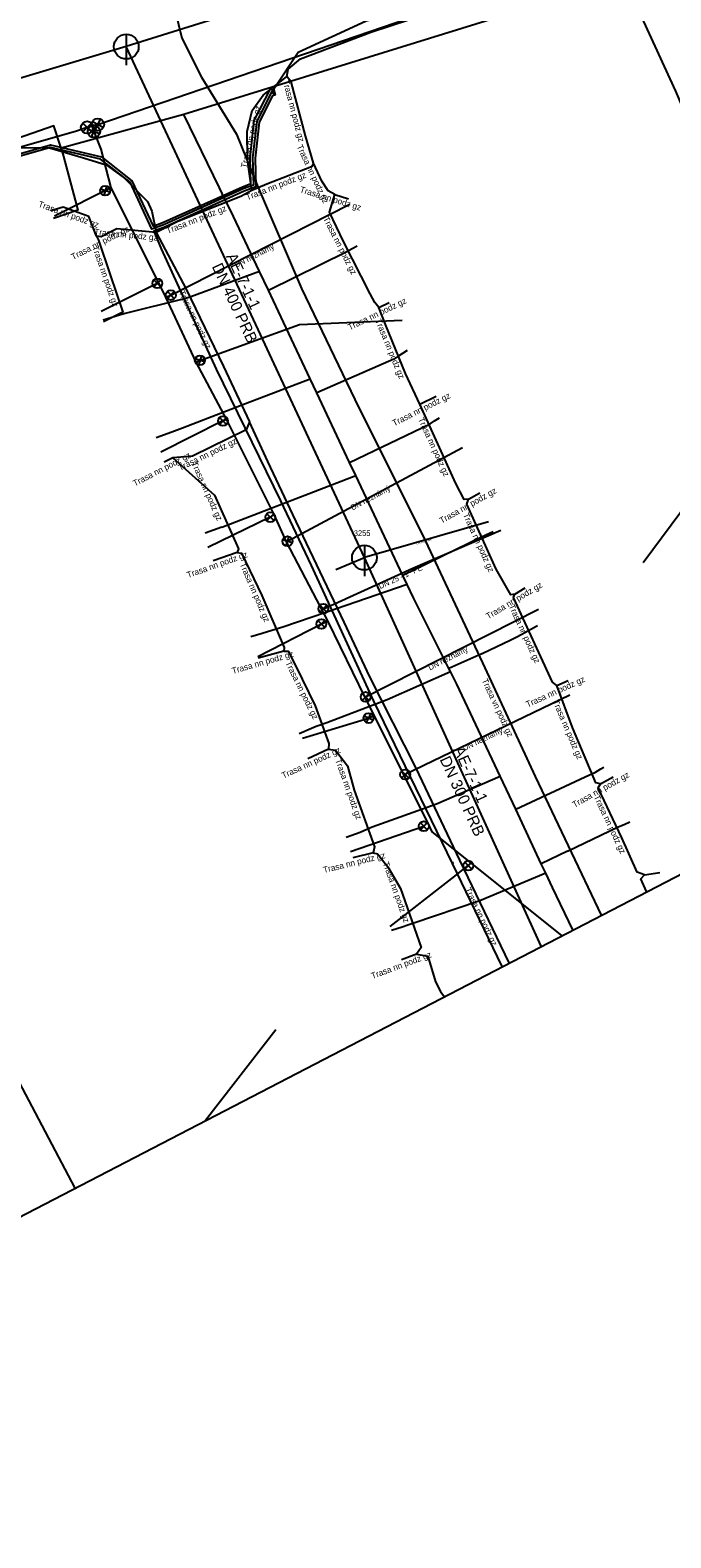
# Model space of a CAD drawing. Extents: x -493753 to -49291, y -1127285 to -112662.
# Drawn here: x -493223.7 to -493171.7, y -1127147 to -1127024.8 of the extents above; entities that cross this region are included whole.
import ezdxf

# ---------------------------------------------------------------- set-up
doc = ezdxf.new("R2010")
doc.units = 0
for name, color, linetype in [('Vrstva 1', 7, 'Continuous'), ('Vrstva 14', 7, 'Continuous'), ('Vrstva 15', 7, 'Continuous'), ('Vrstva 17', 7, 'Continuous'), ('Vrstva 19', 7, 'Continuous'), ('Vrstva 20', 7, 'Continuous'), ('Vrstva 22', 7, 'Continuous'), ('Vrstva 24', 7, 'Continuous'), ('Vrstva 25', 7, 'Continuous'), ('Vrstva 26', 7, 'Continuous'), ('Vrstva 39', 7, 'Continuous'), ('Vrstva 5', 7, 'Continuous'), ('Vrstva 6', 7, 'Continuous'), ('Vrstva 9', 7, 'Continuous')]:
    doc.layers.add(name, color=color, linetype=linetype)

# ---------------------------------------------------------------- blocks, each defined once
blk = doc.blocks.new('_UZAVE')
at = {"layer": 'Vrstva 1'}
for p, q in [((-0.035, -0.035), (0.035, 0.035)), ((0.035, -0.035), (-0.035, 0.035))]:
    blk.add_line(p, q, dxfattribs=at)
for radius in [0.05, 0.0025]:
    blk.add_circle((0, 0), radius, dxfattribs=at)
blk = doc.blocks.new('_UZAV0')
at = {"layer": 'Vrstva 1'}
for p, q in [((-0.035, -0.035), (0.035, 0.035)), ((0.035, -0.035), (-0.035, 0.035))]:
    blk.add_line(p, q, dxfattribs=at)
for radius in [0.05, 0.0025]:
    blk.add_circle((0, 0), radius, dxfattribs=at)
blk = doc.blocks.new('_SACH0')
at = {"layer": 'Vrstva 1'}
blk.add_line((0, 0.05), (0, -0.075), dxfattribs=at)
blk.add_circle((0, 0), 0.05, dxfattribs=at)

msp = doc.modelspace()

# ---------------------------------------------------------------- linework, layer by layer
at = {"layer": 'Vrstva 1'}
for p, q in [((-493204.35, -1127045.83), (-493197.99, -1127042.7)), ((-493194.18, -1127051.44), (-493200.42, -1127054.15)), ((-493197.76, -1127059.8), (-493191.23, -1127056.67)), ((-493208.11, -1127065.04), (-493197.25, -1127060.86)), ((-493208.11, -1127065.04), (-493209.47, -1127065.53)), ((-493187.07, -1127065.86), (-493193.43, -1127068.97)), ((-493184.28, -1127087.92), (-493178.65, -1127085.3)), ((-493180.09, -1127091.32), (-493182.21, -1127092.33))]:
    msp.add_line(p, q, dxfattribs=at)
for points in [[(-493753.13, -1126773.63), (-493540.88, -1127284.87), (-492737.61, -1126868.64), (-492950.39, -1126535.73)], [(-493131.42, -1127030.32), (-493131.54, -1127030.08), (-493135.12, -1127022.73), (-493135.45, -1127022.1), (-493138.54, -1127016.22), (-493141.06, -1127011.41), (-493141.75, -1127010.11), (-493148.64, -1127012.24), (-493150.28, -1127012.75), (-493211.21, -1127031.6)], [(-493211.21, -1127031.6), (-493221.15, -1127034.33), (-493221.76, -1127032.53), (-493224.08, -1127033.32), (-493235.06, -1127037.06), (-493243.7, -1127040), (-493243.18, -1127041.53), (-493248.45, -1127043.29), (-493250.96, -1127044.13), (-493295.19, -1127058.95), (-493308.31, -1127063.27)], [(-493179.64, -1127097.68), (-493181.3, -1127094.25), (-493181.85, -1127093.09), (-493182.21, -1127092.33), (-493184.28, -1127087.92), (-493185.55, -1127085.23), (-493189.06, -1127077.78), (-493189.57, -1127076.76), (-493189.7, -1127076.5), (-493192.58, -1127070.78), (-493193.08, -1127069.71), (-493193.43, -1127068.97), (-493197.25, -1127060.86), (-493197.76, -1127059.8), (-493200.42, -1127054.15), (-493200.95, -1127053.02), (-493203.12, -1127048.42), (-493204.35, -1127045.83), (-493205.07, -1127044.33), (-493207.43, -1127039.35), (-493207.87, -1127038.45), (-493208.31, -1127037.55), (-493211.21, -1127031.6)], [(-493221.15, -1127034.33), (-493220.97, -1127035.01), (-493219.8, -1127039.36), (-493221.78, -1127040.04)], [(-493197.99, -1127042.7), (-493197.56, -1127042.47), (-493197.14, -1127042.24)], [(-493205.07, -1127044.33), (-493210.63, -1127046.37), (-493211.24, -1127046.56), (-493211.3, -1127046.58), (-493215.97, -1127047.73)], [(-493215.97, -1127047.73), (-493216.43, -1127047.87), (-493217.76, -1127048.26)], [(-493193.08, -1127050.72), (-493193.86, -1127051.22), (-493194.18, -1127051.44)], [(-493211.75, -1127057.16), (-493211.32, -1127057), (-493206.19, -1127055.03), (-493200.95, -1127053.02)], [(-493191.23, -1127056.67), (-493190.87, -1127056.44), (-493190.48, -1127056.18)], [(-493213.46, -1127057.79), (-493212.17, -1127057.32), (-493211.75, -1127057.16)], [(-493186.11, -1127065.42), (-493186.7, -1127065.69), (-493186.76, -1127065.72), (-493187.07, -1127065.86)], [(-493193.08, -1127069.71), (-493199.69, -1127071.96), (-493203.17, -1127073.16), (-493204.43, -1127073.54)], [(-493204.43, -1127073.54), (-493204.86, -1127073.67), (-493205.76, -1127073.95)], [(-493182.51, -1127073.06), (-493183.8, -1127073.76), (-493184.24, -1127074)], [(-493184.24, -1127074), (-493184.69, -1127074.21), (-493187.01, -1127075.31), (-493187.03, -1127075.31), (-493189.7, -1127076.5)], [(-493200.46, -1127081.17), (-493199.6, -1127080.88), (-493194.7, -1127079.03), (-493189.57, -1127076.76)], [(-493201.86, -1127081.77), (-493200.86, -1127081.34), (-493200.46, -1127081.17)], [(-493178.65, -1127085.3), (-493177.82, -1127084.92), (-493177.38, -1127084.64), (-493177.14, -1127084.49)], [(-493196.6, -1127089.65), (-493195.94, -1127089.35), (-493190.7, -1127087.47), (-493185.55, -1127085.23)], [(-493180.09, -1127091.32), (-493175.98, -1127089.35), (-493175.48, -1127089.14), (-493175.03, -1127088.94)], [(-493198.04, -1127090.19), (-493196.89, -1127089.76), (-493196.6, -1127089.65)], [(-493181.85, -1127093.09), (-493187.2, -1127095.33), (-493192.62, -1127097.17), (-493193.04, -1127097.32)], [(-493193.04, -1127097.32), (-493193.5, -1127097.46), (-493194.35, -1127097.74)]]:
    msp.add_lwpolyline(points, dxfattribs=at)
at = {"layer": 'Vrstva 14'}
for points in [[(-493161.26, -1127050.88), (-493173.95, -1127067.95)], [(-493238.01, -1127084.61), (-493220.05, -1127118.62)], [(-493209.44, -1127113.12), (-493203.73, -1127105.78)]]:
    msp.add_lwpolyline(points, dxfattribs=at)
at = {"layer": 'Vrstva 15'}
for p, q in [((-493183.43, -1127015.92), (-493215.87, -1127026.1)), ((-493215.87, -1127026.1), (-493243.41, -1127034.33)), ((-493196.56, -1127067.52), (-493215.87, -1127026.1)), ((-493186.5, -1127064.61), (-493196.56, -1127067.52)), ((-493198.87, -1127068.47), (-493196.56, -1127067.52)), ((-493182.21, -1127099.01), (-493196.56, -1127067.52))]:
    msp.add_line(p, q, dxfattribs=at)
at = {"layer": 'Vrstva 20'}
for p, q in [((-493218.18, -1127032.42), (-493144.22, -1127007.09)), ((-493218.66, -1127032.52), (-493219.05, -1127032.65)), ((-493218.66, -1127032.52), (-493218.18, -1127032.42)), ((-493218.66, -1127032.52), (-493218.5, -1127032.97)), ((-493217.14, -1127037.55), (-493221.7, -1127039.84)), ((-493201.81, -1127048.63), (-493193.49, -1127048.27)), ((-493194.46, -1127097.43), (-493189.46, -1127093.52))]:
    msp.add_line(p, q, dxfattribs=at)
for points in [[(-493219.05, -1127032.65), (-493219.91, -1127032.94), (-493249.48, -1127041.42), (-493252.24, -1127042.48), (-493297.85, -1127056.18)], [(-493218.5, -1127032.97), (-493217.94, -1127034.41), (-493217.14, -1127037.55), (-493213.27, -1127045.25), (-493212.7, -1127046.4), (-493210.24, -1127051.68), (-493207.75, -1127056.34), (-493203.9, -1127064.03), (-493202.9, -1127066.25), (-493199.52, -1127072.69), (-493196.53, -1127078.85), (-493193.45, -1127085), (-493191.29, -1127089.33)], [(-493212.7, -1127046.4), (-493212.26, -1127046.24), (-493197.73, -1127038.88)], [(-493213.27, -1127045.25), (-493213.36, -1127045.29), (-493217.91, -1127047.58)], [(-493210.24, -1127051.68), (-493209.9, -1127051.53), (-493201.81, -1127048.63)], [(-493207.75, -1127056.34), (-493208.03, -1127056.44), (-493213.06, -1127058.98)], [(-493202.9, -1127066.25), (-493202.8, -1127066.19), (-493188.61, -1127058.6)], [(-493203.9, -1127064.03), (-493204.19, -1127064.24), (-493209.26, -1127066.69)], [(-493199.99, -1127071.76), (-493199.89, -1127071.66), (-493192.64, -1127068.38), (-493185.48, -1127065.29)], [(-493196.53, -1127078.85), (-493196.46, -1127078.81), (-493182.44, -1127071.69)], [(-493199.52, -1127072.69), (-493200.05, -1127072.9), (-493205.21, -1127075.57)], [(-493179.9, -1127078.67), (-493193.25, -1127085.1), (-493193.36, -1127085.17)], [(-493201.57, -1127082.15), (-493196.22, -1127080.53), (-493195.79, -1127080.32)], [(-493197.68, -1127091.34), (-493191.74, -1127089.29), (-493191.47, -1127088.98)], [(-493191.29, -1127089.33), (-493191.08, -1127089.75), (-493180.56, -1127098.16)], [(-493189.46, -1127093.52), (-493188.13, -1127092.48), (-493187.88, -1127092.19)]]:
    msp.add_lwpolyline(points, dxfattribs=at)
at = {"layer": 'Vrstva 25'}
for points in [[(-493203.78, -1127030.01), (-493203.91, -1127029.51), (-493201.93, -1127026.54), (-493196.42, -1127024.02), (-493192.45, -1127022.88), (-493192.52, -1127022.41), (-493192.27, -1127022.81), (-493171.2, -1127015.41), (-493171.17, -1127015.14), (-493171, -1127015.35), (-493150.3, -1127008.23), (-493147.93, -1127007.71), (-493147.3, -1127007.81), (-493147.29, -1127008.43), (-493147.1, -1127007.84), (-493145.51, -1127008.07), (-493142.62, -1127008.33), (-493140.69, -1127009.48), (-493138.74, -1127011.55), (-493132.11, -1127025.55), (-493132.31, -1127026.61)], [(-493260.22, -1127046.57), (-493260.09, -1127046.32), (-493254.57, -1127044.51), (-493239.33, -1127039.5), (-493225.18, -1127034.99), (-493225.11, -1127034.65), (-493224.84, -1127034.88), (-493222.03, -1127034.07), (-493217.89, -1127035.04), (-493215.41, -1127036.97), (-493213.7, -1127040.65), (-493212.86, -1127040.33), (-493206.46, -1127037.45), (-493205.76, -1127037.19), (-493205.83, -1127035.11), (-493205.49, -1127032.1), (-493204.16, -1127029.47), (-493203.78, -1127030.01)], [(-493203.78, -1127030.01), (-493204.09, -1127029.77), (-493205.29, -1127032.16), (-493205.63, -1127035.12), (-493205.56, -1127037.33), (-493206.38, -1127037.63), (-493212.78, -1127040.51), (-493213.8, -1127040.9), (-493215.57, -1127037.09), (-493217.97, -1127035.22), (-493222.03, -1127034.27), (-493224.95, -1127035.12), (-493239.27, -1127039.69)], [(-493203.78, -1127030.01), (-493204.02, -1127030.08), (-493205.1, -1127032.22), (-493205.43, -1127035.13), (-493205.36, -1127037.47), (-493206.31, -1127037.82), (-493212.7, -1127040.7), (-493213.63, -1127041.05), (-493213.04, -1127042.48), (-493208.58, -1127052.24), (-493203.36, -1127062.91), (-493200.89, -1127068.16), (-493195.82, -1127079.16), (-493189.43, -1127092.31), (-493185.4, -1127100.67)]]:
    msp.add_lwpolyline(points, dxfattribs=at)
at = {"layer": 'Vrstva 26'}
msp.add_line((-493189.31, -1127092.25), (-493189.33, -1127092.26), dxfattribs=at)
at = {"layer": 'Vrstva 39'}
msp.add_lwpolyline([(-493235.73, -1127025.17), (-493229.59, -1127023.36), (-493217.62, -1127019.87), (-493209.8, -1127017.48), (-493201.12, -1127014.06), (-493191.79, -1127010.53), (-493180.27, -1127008.11), (-493179.99, -1127008.93), (-493179.17, -1127010.93), (-493177.18, -1127016.55), (-493176.51, -1127018.4), (-493171.32, -1127029.71), (-493169.32, -1127034.4), (-493165.23, -1127043.1), (-493161.92, -1127050.08), (-493161.26, -1127050.88)], dxfattribs=at)
at = {"layer": 'Vrstva 5'}
for points in [[(-493202.84, -1127028.53), (-493202.74, -1127027.92), (-493201.75, -1127027.08), (-493196.03, -1127024.93), (-493188.11, -1127022.31), (-493177.11, -1127018.57), (-493168.04, -1127015.49), (-493159.49, -1127012.5), (-493152.14, -1127010.18), (-493147.23, -1127009.45), (-493145.09, -1127010.9)], [(-493205.68, -1127037.75), (-493206.04, -1127035.24), (-493206.07, -1127032.97), (-493205.67, -1127031.27), (-493204.77, -1127030.02), (-493203.15, -1127028.75), (-493202.84, -1127028.53)], [(-493200.7, -1127035.55), (-493201.35, -1127033.32), (-493202.5, -1127028.95), (-493202.84, -1127028.53)], [(-493294.6, -1127062.55), (-493296.76, -1127061.82), (-493296.08, -1127060.54), (-493294.79, -1127058.92), (-493292.58, -1127057.01), (-493290.97, -1127055.75), (-493287.24, -1127054.18), (-493281.83, -1127052.27), (-493275.52, -1127050.32), (-493268.05, -1127048.08), (-493261.13, -1127045.75), (-493255.54, -1127044), (-493242.37, -1127040.1), (-493234.97, -1127037.22), (-493227.14, -1127034.67), (-493224.59, -1127034.28), (-493222.11, -1127034.31), (-493219.35, -1127035.1), (-493217.51, -1127035.69), (-493216.02, -1127036.75), (-493214.15, -1127038.64), (-493213.79, -1127039.43), (-493213.44, -1127041.17)], [(-493200.7, -1127035.55), (-493200.86, -1127035.85), (-493204.47, -1127037.26), (-493205.68, -1127037.75)], [(-493198.96, -1127038.09), (-493199.51, -1127037.8), (-493200.02, -1127037.01), (-493200.7, -1127035.55)], [(-493205.68, -1127037.75), (-493206.58, -1127038.25), (-493211.7, -1127040.27), (-493213.44, -1127041.17)], [(-493195.38, -1127047.25), (-493195.71, -1127046.85), (-493196.1, -1127046.13), (-493198.26, -1127041.89), (-493199.38, -1127039.52), (-493198.96, -1127038.09)], [(-493198.96, -1127038.09), (-493197.84, -1127038.44)], [(-493218.28, -1127041.45), (-493218.92, -1127039.86), (-493220.99, -1127039.11), (-493221.99, -1127039.41)], [(-493216.65, -1127040.87), (-493217.92, -1127041.51), (-493218.28, -1127041.45)], [(-493218.28, -1127041.45), (-493218.12, -1127041.78), (-493217.18, -1127044.59), (-493216.14, -1127047.61), (-493217.71, -1127048.4)], [(-493213.44, -1127041.17), (-493216.65, -1127040.87)], [(-493213.44, -1127041.17), (-493211.02, -1127045.77), (-493208, -1127052.03), (-493205.89, -1127056.52)], [(-493195.38, -1127047.25), (-493194.54, -1127046.84)], [(-493192.05, -1127055.08), (-493193.22, -1127052.59), (-493194.85, -1127048.63), (-493195.38, -1127047.25)], [(-493192.05, -1127055.08), (-493190.75, -1127054.43)], [(-493188.11, -1127062.79), (-493188.47, -1127062.81), (-493189.13, -1127061.51), (-493192.05, -1127055.08)], [(-493205.89, -1127056.52), (-493206.15, -1127057.17), (-493210.51, -1127059.29), (-493212.11, -1127059.43)], [(-493184.83, -1127100.37), (-493188.82, -1127092.05), (-493192.35, -1127084.58), (-493196.11, -1127077.17), (-493198.19, -1127072.75), (-493202.36, -1127064.03), (-493204.38, -1127059.72), (-493205.89, -1127056.52)], [(-493212.11, -1127059.43), (-493212.79, -1127059.79)], [(-493212.11, -1127059.43), (-493208.72, -1127062.46), (-493206.77, -1127066.8), (-493206.88, -1127067.09)], [(-493188.11, -1127062.79), (-493187.19, -1127062.27)], [(-493184.35, -1127070.47), (-493184.69, -1127070.53), (-493185.87, -1127068.45), (-493188.25, -1127063.19), (-493188.11, -1127062.79)], [(-493206.88, -1127067.09), (-493208.83, -1127067.78)], [(-493206.88, -1127067.09), (-493206.54, -1127067.15), (-493204.89, -1127070.58), (-493203.07, -1127074.81), (-493203.1, -1127075.1)], [(-493184.35, -1127070.47), (-493183.51, -1127069.97)], [(-493180.95, -1127077.89), (-493181.3, -1127077.62), (-493184.47, -1127070.75), (-493184.35, -1127070.47)], [(-493203.1, -1127075.1), (-493205.17, -1127075.68)], [(-493203.1, -1127075.1), (-493202.73, -1127075.11), (-493202.13, -1127076.32), (-493200.55, -1127079.53), (-493199.45, -1127082.59), (-493199.47, -1127083.05)], [(-493180.95, -1127077.89), (-493180.02, -1127077.47)], [(-493177.4, -1127085.86), (-493177.78, -1127085.76), (-493179.69, -1127081.29), (-493180.95, -1127077.89)], [(-493199.47, -1127083.05), (-493201.14, -1127083.82)], [(-493199.47, -1127083.05), (-493198.9, -1127083.13), (-493197.94, -1127084.4), (-493197.38, -1127086.37), (-493195.74, -1127090.97), (-493195.86, -1127091.44)], [(-493173.84, -1127093.23), (-493174.43, -1127093.02), (-493175.69, -1127090.23), (-493177.59, -1127086.18), (-493177.4, -1127085.86)], [(-493177.4, -1127085.86), (-493176.37, -1127085.28)], [(-493195.86, -1127091.44), (-493197.5, -1127091.85)], [(-493195.86, -1127091.44), (-493195.49, -1127091.52), (-493194.67, -1127092.58), (-493193.64, -1127094.34), (-493191.95, -1127099.12), (-493192.32, -1127099.66)], [(-493173.67, -1127094.59), (-493174.13, -1127093.55), (-493173.84, -1127093.23)], [(-493173.84, -1127093.23), (-493172.59, -1127093.05)], [(-493192.32, -1127099.66), (-493193.56, -1127100.12)], [(-493192.32, -1127099.66), (-493191.41, -1127099.81), (-493190.79, -1127101.89), (-493190.38, -1127102.7), (-493190.1, -1127103.1)]]:
    msp.add_lwpolyline(points, dxfattribs=at)
at = {"layer": 'Vrstva 6'}
msp.add_lwpolyline([(-493211.91, -1127023.2), (-493211.36, -1127025.41), (-493209.78, -1127028.57), (-493206.92, -1127033.19), (-493205.25, -1127037.34), (-493201.67, -1127045.7), (-493197.33, -1127054.7), (-493191.61, -1127066.18), (-493186.8, -1127076.44), (-493182.72, -1127085.25), (-493177.36, -1127096.5)], dxfattribs=at)

# ---------------------------------------------------------------- block references
at = {"layer": 'Vrstva 17', "xscale": 19.997500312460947, "yscale": 19.997500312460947}
for p in [(-493215.87, -1127026.1), (-493196.56, -1127067.52)]:
    msp.add_blockref('_SACH0', p, dxfattribs=at)
at = {"layer": 'Vrstva 22'}
for name, p, xscale, yscale in [('_UZAVE', (-493219.05, -1127032.65), 9.998750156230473, 9.998750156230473), ('_UZAV0', (-493213.36, -1127045.29), 7.999000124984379, 7.999000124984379), ('_UZAV0', (-493212.26, -1127046.24), 7.999000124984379, 7.999000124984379), ('_UZAV0', (-493208.03, -1127056.44), 7.999000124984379, 7.999000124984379), ('_UZAV0', (-493204.19, -1127064.24), 7.999000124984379, 7.999000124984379), ('_UZAV0', (-493199.89, -1127071.66), 7.999000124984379, 7.999000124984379), ('_UZAV0', (-493200.05, -1127072.9), 7.999000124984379, 7.999000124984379), ('_UZAV0', (-493196.46, -1127078.81), 7.999000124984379, 7.999000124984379), ('_UZAV0', (-493193.25, -1127085.1), 7.999000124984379, 7.999000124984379), ('_UZAV0', (-493191.74, -1127089.29), 7.999000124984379, 7.999000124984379), ('_UZAV0', (-493188.13, -1127092.48), 7.999000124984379, 7.999000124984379)]:
    msp.add_blockref(name, p, dxfattribs=dict(at, xscale=xscale, yscale=yscale))
for name, p, xscale, yscale, rotation in [('_UZAVE', (-493218.18, -1127032.42), 9.998750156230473, 9.998750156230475, 18.494008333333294), ('_UZAVE', (-493218.5, -1127032.97), 9.998750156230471, 9.998750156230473, -66.575794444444), ('_UZAV0', (-493217.58, -1127037.77), 7.999000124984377, 7.999000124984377, 116.65811944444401), ('_UZAV0', (-493209.9, -1127051.53), 7.999000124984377, 7.999000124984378, 116.45170000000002), ('_UZAV0', (-493202.8, -1127066.19), 7.999000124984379, 7.999000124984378, 116.97193055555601), ('_UZAV0', (-493196.22, -1127080.53), 7.999000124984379, 7.999000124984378, 19.6060861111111)]:
    msp.add_blockref(name, p, dxfattribs=dict(at, xscale=xscale, yscale=yscale, rotation=rotation))

# ---------------------------------------------------------------- texts
at = {"layer": 'Vrstva 19'}
for s, height, rotation, p in [('AE-7-1-1', 0.91, 294.9946, (-493207.81, -1127043.09)), ('DN 400 PRB', 0.91, 294.9946, (-493208.95, -1127043.91)), ('DN 200 KAM', 0.16, 16.1376, (-493192.32, -1127066.46)), ('AE-7-1-1', 0.91, 294.5063, (-493189.35, -1127083.06)), ('DN 300 PRB', 0.91, 294.5063, (-493190.47, -1127083.87))]:
    msp.add_text(s, height=height, rotation=rotation, dxfattribs=at).set_placement(p)
msp.add_text('3255', height=0.455, dxfattribs=at).set_placement((-493197.42, -1127065.76))
at = {"layer": 'Vrstva 24'}
for s, rotation, p in [('DN neznámý', 26.8479, (-493206.96, -1127044.04)), ('DN neznámý', 28.1435, (-493197.51, -1127063.7)), ("DN 25 - 1'' PE", 24.3685, (-493195.28, -1127070.07)), ('DN neznámý', 26.9471, (-493191.24, -1127076.67)), ('DN neznámý', 25.7187, (-493188.46, -1127083.2))]:
    msp.add_text(s, height=0.455, rotation=rotation, dxfattribs=at).set_placement(p)
at = {"layer": 'Vrstva 9'}
for s, rotation, p in [('Trasa nn podz gz', 284.7568, (-493203.19, -1127028.87)), ('Trasa nn podz gz', 76.8064, (-493206.11, -1127035.98)), ('Trasa nn podz gz', 294.9823, (-493202.06, -1127034.18)), ('Trasa nn podz gz', 21.3125, (-493206.05, -1127038.57)), ('Trasa nn podz gz', 343.0157, (-493201.84, -1127037.89)), ('Trasa nn podz gz', 340.2865, (-493223.06, -1127039.06)), ('Trasa nn podz gz', 21.4612, (-493212.51, -1127041.28)), ('Trasa nn podz gz', 27.0331, (-493220.19, -1127043.4)), ('Trasa nn podz gz', 297.0383, (-493199.93, -1127040.04)), ('Trasa nn podz gz', 354.6719, (-493218.49, -1127041.35)), ('Trasa nn podz gz', 289.0772, (-493218.64, -1127042.35)), ('Trasa nn podz gz', 295.7201, (-493211.63, -1127046)), ('Trasa nn podz gz', 25.6937, (-493197.75, -1127049.1)), ('Trasa nn podz gz', 292.4266, (-493195.69, -1127048.3)), ('Trasa nn podz gz', 26.8469, (-493194.14, -1127056.88)), ('Trasa nn podz gz', 294.3862, (-493192.22, -1127056.29)), ('Trasa nn podz gz', 27.5355, (-493215.17, -1127061.76)), ('Trasa nn podz gz', 25.9469, (-493211.51, -1127060.5)), ('Trasa nn podz gz', 294.2008, (-493210.61, -1127059.87)), ('Trasa nn podz gz', 29.4636, (-493190.29, -1127064.78)), ('Trasa nn podz gz', 294.3387, (-493188.58, -1127064.04)), ('Trasa nn podz gz', 19.4416, (-493210.86, -1127069.18)), ('Trasa nn podz gz', 293.3376, (-493206.69, -1127068.05)), ('Trasa nn podz gz', 30.8938, (-493186.51, -1127072.53)), ('Trasa nn podz gz', 294.7593, (-493184.87, -1127071.44)), ('Trasa nn podz gz', 15.9051, (-493207.23, -1127076.95)), ('Trasa nn podz gz', 296.2581, (-493202.99, -1127076.05)), ('Trasa vn podz gz', 294.8493, (-493187.05, -1127077.46)), ('Trasa nn podz gz', 24.3046, (-493183.32, -1127079.67)), ('Trasa nn podz gz', 293.1228, (-493181.3, -1127079.17)), ('Trasa nn podz gz', 24.568, (-493203.13, -1127085.44)), ('Trasa nn podz gz', 289.642, (-493198.94, -1127083.93)), ('Trasa nn podz gz', 29.3419, (-493179.52, -1127087.8)), ('Trasa nn podz gz', 295.1384, (-493177.97, -1127086.9)), ('Trasa nn podz gz', 13.7735, (-493199.84, -1127093.09)), ('Trasa nn podz gz', 289.5246, (-493195.07, -1127092.28)), ('Trasa nn podz gz', 295.677, (-493188.42, -1127094.4)), ('Trasa nn podz gz', 20.3231, (-493195.91, -1127101.68))]:
    msp.add_text(s, height=0.5, rotation=rotation, dxfattribs=at).set_placement(p)

doc.saveas('drawing.dxf')
